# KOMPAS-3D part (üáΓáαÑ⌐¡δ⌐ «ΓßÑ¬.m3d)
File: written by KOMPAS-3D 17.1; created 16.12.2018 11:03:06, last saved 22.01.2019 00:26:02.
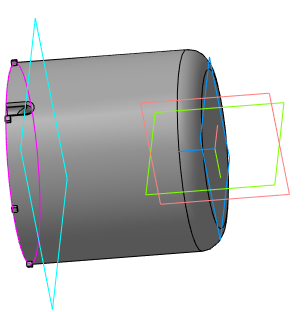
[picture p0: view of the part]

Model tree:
1. Тело детали
2. Операция выдавливания:1
     Расстояние 1 = 74.5
3. Пазы Аккумуляторов
4. Вырезать элемент выдавливания:1
     Расстояние 1 = 72.5
5. Паз для платы
6. Вырезать элемент выдавливания:2
     Расстояние 1 = 62.81
7. Эскиз:6
8. Скругление:1
     Радиус = 8
9. Эскиз:9
10. Операция выдавливания:2
     Расстояние 2 = 2
11. Эскиз:10
12. Смещенная плоскость:3
     Расстояние = 8
13. Эскиз:11
14. Вырезать элемент вращения:3
     Угол 1 = 360
15. Эскиз:12
16. Вырезать элемент выдавливания:3
     Расстояние 1 = 8
17. Скругление:2
     Радиус = 2
18. Скругление:3
     Радиус = 2
19. Фаска:2
     Угол = 45; Длина 1 = 1; Длина 2 = 1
